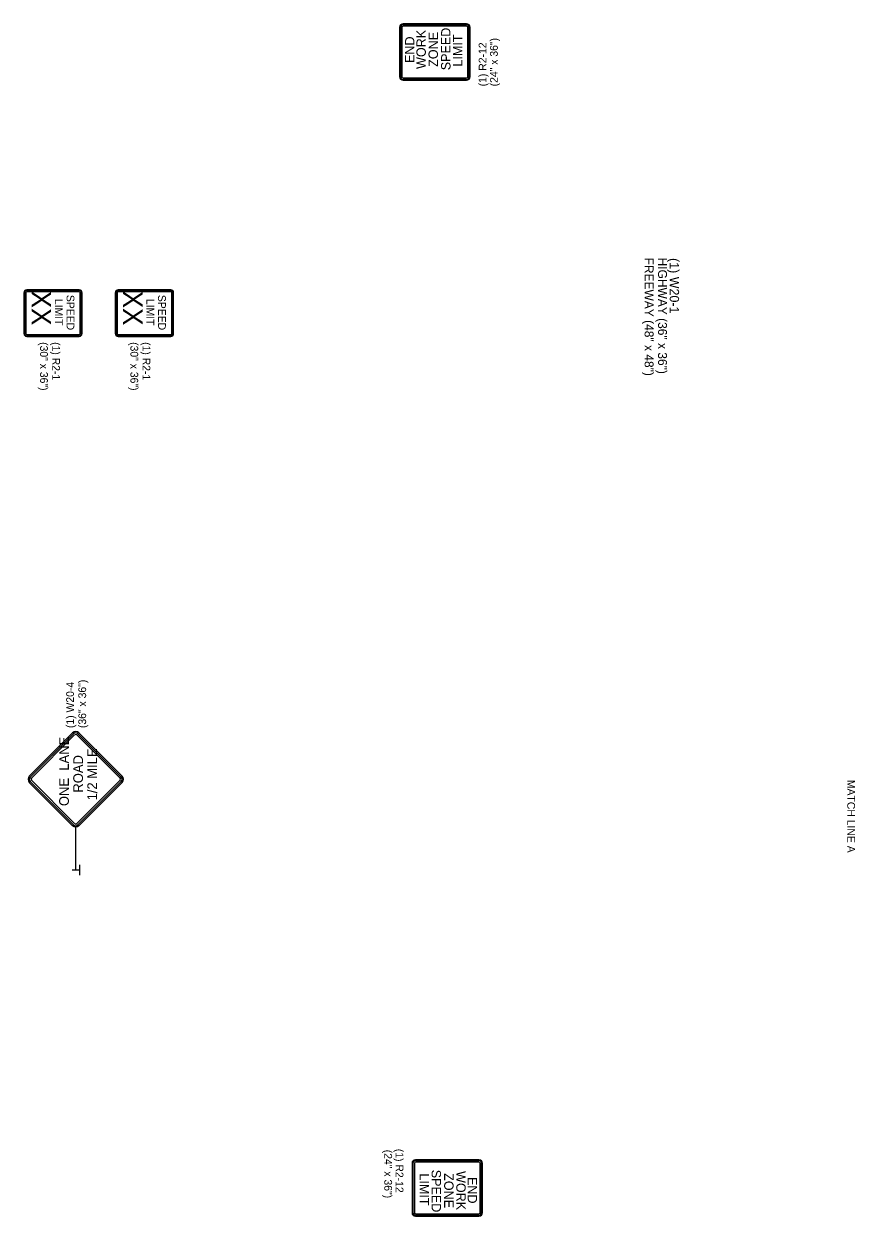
# Model space of a CAD drawing. Extents: x 1926586 to 1930787, y 596452 to 599566.
# Drawn here: x 1927226 to 1927867, y 596697 to 597617 of the extents above; entities that cross this region are included whole.
import ezdxf

# ---------------------------------------------------------------- set-up
doc = ezdxf.new("R2010")
doc.units = 0
for name, color, linetype in [('Default', 7, 'Continuous'), ('P_TC_Signs_Permanent', 7, 'Continuous'), ('P_TC_Signs_Temporary', 7, 'Continuous'), ('R_Border', 7, 'Continuous')]:
    doc.layers.add(name, color=color, linetype=linetype)

msp = doc.modelspace()

# ---------------------------------------------------------------- linework, layer by layer
at = {"layer": 'Default'}
for p, q in [((1927268.28, 596963.91), (1927262.82, 596963.91)), ((1927268.4, 596967.89), (1927268.4, 596959.89))]:
    msp.add_line(p, q, dxfattribs=at)
at = {"layer": 'P_TC_Signs_Permanent'}
for p, q in [((1927567.2, 597616.99), (1927518.26, 597616.99)), ((1927567.2, 597616.31), (1927518.26, 597616.31)), ((1927515.54, 597614.27), (1927515.54, 597576.2)), ((1927516.22, 597614.27), (1927516.22, 597576.2)), ((1927517.36, 597614.27), (1927517.36, 597576.2)), ((1927567.2, 597615.17), (1927518.26, 597615.17)), ((1927568.11, 597576.2), (1927568.11, 597614.27)), ((1927569.24, 597576.2), (1927569.24, 597614.27)), ((1927569.92, 597576.2), (1927569.92, 597614.27)), ((1927518.26, 597575.3), (1927567.2, 597575.3)), ((1927518.26, 597574.17), (1927567.2, 597574.17)), ((1927518.26, 597573.49), (1927567.2, 597573.49)), ((1927225.53, 597409.49), (1927225.53, 597377.99)), ((1927226.1, 597409.49), (1927226.1, 597377.99)), ((1927227.03, 597409.49), (1927227.03, 597377.99)), ((1927268.28, 597411.74), (1927227.78, 597411.74)), ((1927268.28, 597411.18), (1927227.78, 597411.18)), ((1927268.28, 597410.24), (1927227.78, 597410.24)), ((1927269.03, 597377.99), (1927269.03, 597409.49)), ((1927269.97, 597377.99), (1927269.97, 597409.49)), ((1927270.53, 597377.99), (1927270.53, 597409.49)), ((1927296.14, 597409.49), (1927296.14, 597377.99)), ((1927296.71, 597409.49), (1927296.71, 597377.99)), ((1927297.64, 597409.49), (1927297.64, 597377.99)), ((1927338.89, 597411.74), (1927298.39, 597411.74)), ((1927338.89, 597411.18), (1927298.39, 597411.18)), ((1927338.89, 597410.24), (1927298.39, 597410.24)), ((1927339.64, 597377.99), (1927339.64, 597409.49)), ((1927340.58, 597377.99), (1927340.58, 597409.49)), ((1927341.14, 597377.99), (1927341.14, 597409.49)), ((1927227.78, 597377.24), (1927268.28, 597377.24)), ((1927298.39, 597377.24), (1927338.89, 597377.24)), ((1927227.78, 597376.3), (1927268.28, 597376.3)), ((1927227.78, 597375.74), (1927268.28, 597375.74)), ((1927298.39, 597376.3), (1927338.89, 597376.3)), ((1927298.39, 597375.74), (1927338.89, 597375.74)), ((1927525.13, 596737.64), (1927525.13, 596699.57)), ((1927525.81, 596737.64), (1927525.81, 596699.57)), ((1927526.94, 596737.64), (1927526.94, 596699.57)), ((1927576.78, 596740.35), (1927527.85, 596740.35)), ((1927576.78, 596739.67), (1927527.85, 596739.67)), ((1927576.78, 596738.54), (1927527.85, 596738.54)), ((1927577.69, 596699.57), (1927577.69, 596737.64)), ((1927578.82, 596699.57), (1927578.82, 596737.64)), ((1927579.5, 596699.57), (1927579.5, 596737.64)), ((1927527.85, 596698.67), (1927576.78, 596698.67)), ((1927527.85, 596697.53), (1927576.78, 596697.53)), ((1927527.85, 596696.85), (1927576.78, 596696.85))]:
    msp.add_line(p, q, dxfattribs=at)
for centre, radius, start, end in [((1927518.26, 597614.27), 2.72, 90, 180), ((1927518.26, 597614.27), 2.04, 90, 180), ((1927567.2, 597614.27), 2.72, 360, 90), ((1927567.2, 597614.27), 2.04, 360, 90), ((1927518.26, 597614.27), 0.906, 90, 180), ((1927567.2, 597614.27), 0.906, 360, 90), ((1927518.26, 597576.2), 2.72, 180, 270), ((1927518.26, 597576.2), 2.04, 180, 270), ((1927518.26, 597576.2), 0.906, 180, 270), ((1927567.2, 597576.2), 2.72, 270, 360), ((1927567.2, 597576.2), 2.04, 270, 360), ((1927567.2, 597576.2), 0.906, 270, 360), ((1927227.78, 597409.49), 2.25, 90, 180), ((1927227.78, 597409.49), 1.69, 90, 180), ((1927227.78, 597409.49), 0.75, 90, 180), ((1927268.28, 597409.49), 2.25, 360, 90), ((1927268.28, 597409.49), 1.69, 360, 90), ((1927268.28, 597409.49), 0.75, 360, 90), ((1927298.39, 597409.49), 2.25, 90, 180), ((1927298.39, 597409.49), 1.69, 90, 180), ((1927298.39, 597409.49), 0.75, 90, 180), ((1927338.89, 597409.49), 2.25, 360, 90), ((1927338.89, 597409.49), 1.69, 360, 90), ((1927338.89, 597409.49), 0.75, 360, 90), ((1927227.78, 597377.99), 2.25, 180, 270), ((1927227.78, 597377.99), 1.69, 180, 270), ((1927227.78, 597377.99), 0.75, 180, 270), ((1927268.28, 597377.99), 2.25, 270, 360), ((1927268.28, 597377.99), 1.69, 270, 360), ((1927268.28, 597377.99), 0.75, 270, 360), ((1927298.39, 597377.99), 2.25, 180, 270), ((1927298.39, 597377.99), 1.69, 180, 270), ((1927298.39, 597377.99), 0.75, 180, 270), ((1927338.89, 597377.99), 2.25, 270, 360), ((1927338.89, 597377.99), 1.69, 270, 360), ((1927338.89, 597377.99), 0.75, 270, 360), ((1927527.85, 596737.64), 2.72, 90, 180), ((1927527.85, 596737.64), 2.04, 90, 180), ((1927527.85, 596737.64), 0.906, 90, 180), ((1927576.78, 596737.64), 2.72, 360, 90), ((1927576.78, 596737.64), 2.04, 360, 90), ((1927576.78, 596737.64), 0.906, 360, 90), ((1927527.85, 596699.57), 2.72, 180, 270), ((1927527.85, 596699.57), 2.04, 180, 270), ((1927527.85, 596699.57), 0.906, 180, 270), ((1927576.78, 596699.57), 2.72, 270, 360), ((1927576.78, 596699.57), 2.04, 270, 360), ((1927576.78, 596699.57), 0.906, 270, 360)]:
    msp.add_arc(centre, radius, start, end, dxfattribs=at)
at = {"layer": 'P_TC_Signs_Temporary'}
for p, q in [((1927229.75, 597036.39), (1927263.16, 597069.8)), ((1927230.41, 597035.73), (1927263.82, 597069.14)), ((1927231.34, 597034.8), (1927264.75, 597068.21)), ((1927266.34, 597068.21), (1927299.75, 597034.8)), ((1927267.27, 597069.14), (1927300.68, 597035.73)), ((1927267.93, 597069.8), (1927301.35, 597036.39)), ((1927263.16, 596998.2), (1927229.75, 597031.62)), ((1927263.82, 596998.87), (1927230.41, 597032.28)), ((1927264.75, 596999.8), (1927231.34, 597033.21)), ((1927299.75, 597033.21), (1927266.34, 596999.8)), ((1927300.68, 597032.28), (1927267.27, 596998.87)), ((1927301.35, 597031.62), (1927267.93, 596998.2))]:
    msp.add_line(p, q, dxfattribs=at)
for centre, radius, start, end in [((1927265.55, 597067.41), 3.37, 45, 135), ((1927265.55, 597067.41), 2.44, 45, 135), ((1927265.55, 597067.41), 1.12, 45, 135), ((1927232.14, 597034), 3.37, 135, 225), ((1927298.96, 597034), 3.37, 315, 45), ((1927232.14, 597034), 2.44, 135, 225), ((1927232.14, 597034), 1.13, 135, 225), ((1927298.96, 597034), 1.13, 315, 45), ((1927298.96, 597034), 2.44, 315, 45), ((1927265.55, 597000.59), 1.12, 225, 315), ((1927265.55, 597000.59), 3.37, 225, 315), ((1927265.55, 597000.59), 2.44, 225, 315)]:
    msp.add_arc(centre, radius, start, end, dxfattribs=at)
at = {"layer": 'R_Border'}
msp.add_line((1927265.55, 596963.91), (1927265.55, 596997.22), dxfattribs=at)

# ---------------------------------------------------------------- texts
at = {"layer": 'Default'}
msp.add_text('MATCH LINE A', height=6, rotation=270, dxfattribs=at).set_placement((1927861.02, 597033.54))
at = {"layer": 'P_TC_Signs_Permanent'}
for s, height, rotation, p in [('END', 7.251, 90, (1927526.95, 597586.78)), ('WORK', 7.251, 90, (1927535.77, 597582.18)), ('ZONE', 7.251, 90, (1927545.12, 597583.8)), ('SPEED', 7.251, 90, (1927554.81, 597581.17)), ('LIMIT', 7.251, 90, (1927564.03, 597584.01)), ('XX', 15, 270, (1927231.53, 597411.04)), ('SPEED', 6, 270, (1927258.53, 597407.81)), ('XX', 15, 270, (1927302.14, 597411.04)), ('SPEED', 6, 270, (1927329.14, 597407.81)), ('LIMIT', 6, 270, (1927249.53, 597404.72)), ('LIMIT', 6, 270, (1927320.14, 597404.72)), ('LIMIT', 7.251, 270, (1927531.02, 596729.83)), ('SPEED', 7.251, 270, (1927540.24, 596732.67)), ('ZONE', 7.251, 270, (1927549.92, 596730.04)), ('WORK', 7.251, 270, (1927559.27, 596731.66)), ('END', 7.251, 270, (1927568.09, 596727.06))]:
    msp.add_text(s, height=height, rotation=rotation, dxfattribs=at).set_placement(p)
at = {"layer": 'P_TC_Signs_Temporary'}
for s, p in [('ONE  LANE', (1927260.3, 597013.3)), ('1/2 MILE', (1927282.05, 597017.69)), ('ROAD', (1927271.17, 597023.7))]:
    msp.add_text(s, height=7.5, rotation=90, dxfattribs=at).set_placement(p)
at = {"layer": 'R_Border'}
for s, height, rotation, p in [('(1) R2-12', 6, 90, (1927582.57, 597568.75)), ('(24" x 36")', 5.9996, 90, (1927591.32, 597568.75)), ('FREEWAY (48" x 48")', 6.912, 270, (1927704.62, 597436.61)), ('HIGHWAY (36" x 36")', 6.912, 270, (1927714.99, 597436.61)), ('(1) W20-1', 7.2, 270, (1927724.01, 597436.25)), ('(30" x 36")', 5.9996, 270, (1927238.08, 597371.36)), ('(1) R2-1', 6, 270, (1927247.44, 597371.36)), ('(30" x 36")', 5.9996, 270, (1927307.79, 597371.36)), ('(1) R2-1', 6, 270, (1927317.15, 597371.36)), ('(36" x 36")', 6, 90, (1927273.6, 597073.51)), ('(1) W20-4', 6, 90, (1927264.23, 597073.51)), ('(24" x 36")', 5.9996, 270, (1927503.72, 596748.09)), ('(1) R2-12', 6, 270, (1927512.47, 596748.83))]:
    msp.add_text(s, height=height, rotation=rotation, dxfattribs=at).set_placement(p)

doc.saveas('drawing.dxf')
